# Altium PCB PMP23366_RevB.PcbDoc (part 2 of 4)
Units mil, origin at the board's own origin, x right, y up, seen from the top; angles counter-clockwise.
Board outline 6500 x 4250 mil, 4 copper layers (Top Layer 1, Inner Layer 2, Inner Layer 3, Bottom Layer 1), stack 75.824 mil thick; 370 components, 218 nets, 1221 pads, 351 vias.
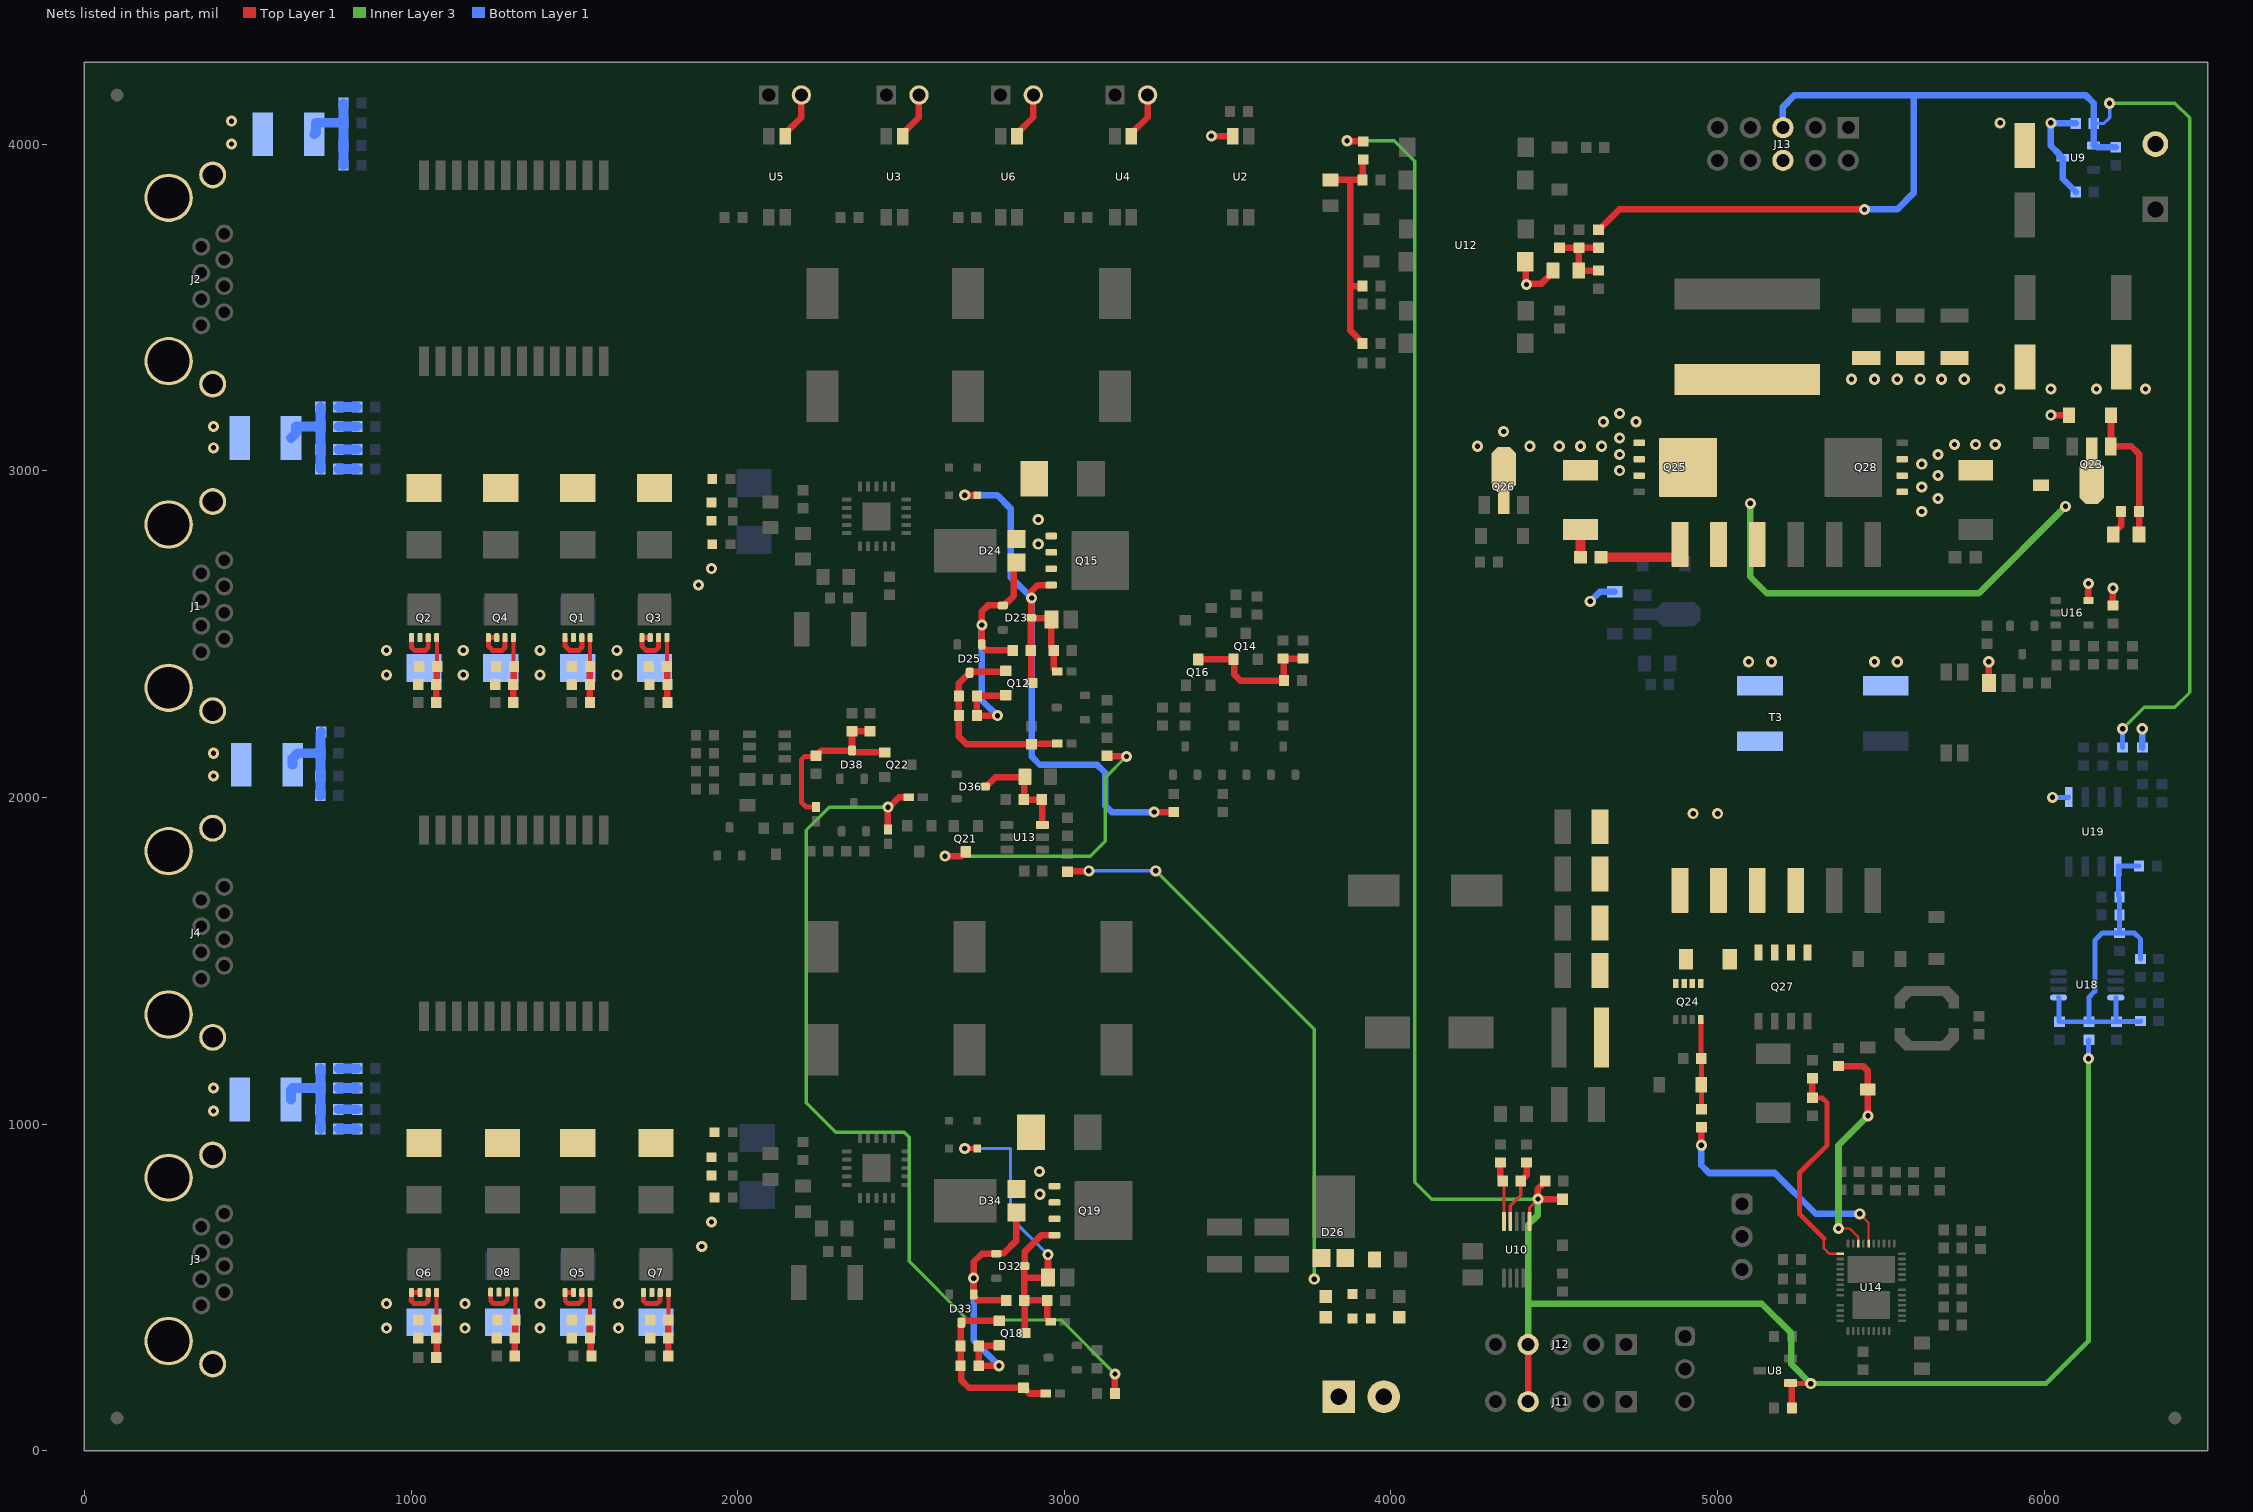
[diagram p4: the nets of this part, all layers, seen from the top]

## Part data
C1 C2 C13 C14 C39 C40: library part CMP-0007053-4, "CAP, CERM, 1000 pF, 100 V, +/- 10%, X7R, 0603", Cap_Case=0603, Manufacturer=TDK, PartNumber=C1608X7R2A102K080AA, Supplier Part Number 1=445-1298-1-ND, TempCo=X7R, Tolerance_%=10%, Value1=Unknown, Value2=100V, ValueDisplayed=1000pF
C3 C4 C5 C6 C15 C16 C17 C18: library part CMP-0007209-4, "CAP, CERM, 330 pF, 50 V, +/- 5%, C0G/NP0, 0603", Cap_Case=0603, Manufacturer=MuRata, PartNumber=GRM1885C1H331JA01D, Supplier Part Number 1=490-1439-1-ND, TempCo=C0G/NP0, Tolerance_%=5%, Value1=Unknown, Value2=50V, ValueDisplayed=330pF
C7 C8 C9 C10 C19 C20 C21 C22: library part CMP-0007468-5, "CAP, CERM, 0.01 uF, 100 V, +/- 10%, X7R, 0603", Cap_Case=0603, Manufacturer=MuRata, PartNumber=GRM188R72A103KA01D, Supplier Part Number 1=GRM188R72A103KA01D-ND, TempCo=X7R, Tolerance_%=10%, Value1=Unknown, Value2=100V, ValueDisplayed=0.01uF
C11 C12 C23 C24: library part CMP-0009438-2, "CAP, CERM, 1000 pF, 2000 V, +/- 10%, X7R, 1812", Cap_Case=1812, Manufacturer=MuRata, PartNumber=GR443QR73D102KW01L, TempCo=X7R, Tolerance_%=10%, Value1=Unknown, Value2=2000V, ValueDisplayed=1000pF
C25 C26 C34 C35 C36 C87 C88: library part CMP-0012603-3, "CAP, Polymer Hybrid, 47 uF, 80 V, +/- 20%, 36 milliohm, 10x10 SMD", Manufacturer=Panasonic, Supplier Part Number 1=P15469CT-ND, Tolerance_%=20%, Value1="36 ohm", Value2=80V, ValueDisplayed=47uF
C27 C38 C41 C57 C75: library part CMP-0007886-2, "CAP, CERM, 0.1 uF, 100 V, +/- 10%, X7R, 0805", Cap_Case=0805, Manufacturer=TDK, PartNumber=C2012X7R2A104K125AA, Supplier Part Number 1=445-1418-1-ND, TempCo=X7R, Tolerance_%=10%, Value1="0.020726 ohm", Value2=100V, ValueDisplayed=0.1uF
C28 C30 C42 C44 C56 C73 C96: library part CMP-0007432-5, "CAP, CERM, 1000 pF, 50 V, +/- 10%, X7R, 0603", Cap_Case=0603, Manufacturer=MuRata, PartNumber=GRM188R71H102KA01D, Supplier Part Number 1=490-1494-1-ND, TempCo=X7R, Tolerance_%=10%, Value1=Unknown, Value2=50V, ValueDisplayed=1000pF
C29 C43: library part CMP-0007887-2, "CAP, CERM, 0.047 uF, 100 V, +/- 10%, X7R, 0805", Cap_Case=0805, Manufacturer=TDK, PartNumber=C2012X7R2A473K125AA, Supplier Part Number 1=445-2276-1-ND, TempCo=X7R, Tolerance_%=10%, Value1="0.049089 ohm", Value2=100V, ValueDisplayed=0.047uF
C31 C55 C89: library part CMP-0007043-4, "CAP, CERM, 0.01 uF, 50 V, +/- 10%, X7R, 0603", Cap_Case=0603, Manufacturer=TDK, PartNumber=C1608X7R1H103K080AA, Supplier Part Number 1=445-1311-1-ND, TempCo=X7R, Tolerance_%=10%, Value1="0.0539 ohm", Value2=50V, ValueDisplayed=0.01uF
C32 C33 C58 C59 C60 C61 C95: library part CMP-0009232-2, "CAP, CERM, 2.2 uF, 100 V, +/- 10%, X7R, 1210", Cap_Case=1210, Manufacturer=MuRata, PartNumber=GRM32ER72A225KA35L, Supplier Part Number 1=490-3385-1-ND, TempCo=X7R, Tolerance_%=10%, Value1="0.007 ohm", Value2=100V, ValueDisplayed=2.2uF
C37: library part CMP-0012602-3, "CAP, Polymer Hybrid, 22 uF, 80 V, +/- 20%, 45 milliohm, 8x10 SMD", Manufacturer=Panasonic, Supplier Part Number 1=P15468CT-ND, Tolerance_%=20%, Value1="45 ohm", Value2=80V, ValueDisplayed=22uF
C45 C46 C47 C48 C49 C52 C53 C54 C71 C74 C80 C81 C82 C90 C91: library part CMP-0006837-4, "CAP, CERM, 0.1 uF, 50 V, +/- 10%, X7R, 0603", Cap_Case=0603, Manufacturer="Wurth Elektronik", TempCo=X7R, Tolerance_%=10%, Value1=Unknown, Value2=50V, ValueDisplayed=0.1uF
C50 C51 C86: library part CMP-0008412-2, "CAP, CERM, 1 uF, 25 V, +/- 10%, X7R, 0805", Cap_Case=0805, Manufacturer="Taiyo Yuden", Supplier Part Number 1=587-1281-1-ND, TempCo=X7R, Tolerance_%=10%, Value1=Unknown, Value2=25V, ValueDisplayed=1uF
C62 C77: library part CMP-0009294-2, "CAP, CERM, 4700 pF, 2000 V, +/- 10%, X7R, 1812", Cap_Case=1812, Manufacturer=AVX, PartNumber=1812GC472KA1, Supplier Part Number 1=581-1812GC472KA11A, TempCo=X7R, Tolerance_%=10%, Value1=Unknown, Value2=2000V, ValueDisplayed=4700pF
C63 C94: library part CMP-0006834-5, "CAP, CERM, 470 pF, 50 V, +/- 10%, X7R, 0603", Cap_Case=0603, Manufacturer="Wurth Elektronik", Supplier Part Number 1=710-885012206081, TempCo=X7R, Tolerance_%=10%, Value1=Unknown, Value2=50V, ValueDisplayed=470pF
C64: library part CMP-0008975-2, "CAP, CERM, 0.047 uF, 250 V, +/- 10%, X7R, 1206", Cap_Case=1206, Manufacturer=MuRata, Supplier Part Number 1=490-3538-1-ND, TempCo=X7R, Tolerance_%=10%, Value1=Unknown, Value2=250V, ValueDisplayed=0.047uF
C65 C66 C67: library part CMP-0012073-3, "CAP, Aluminum Polymer, 220 uF, 10 V, +/- 20%, 0.02 ohm, F61 SMD", Manufacturer=Panasonic, Supplier Part Number 1=P16445CT-ND, Tolerance_%=20%, Value1="0.02 ohm", Value2=10V, ValueDisplayed=220uF
C68 C69 C70: library part CMP-0009082-2, "CAP, CERM, 100 uF, 10 V, +/- 20%, X5R, 1210", Cap_Case=1210, Manufacturer="Wurth Elektronik", Supplier Part Number 1=399-11631-1-ND, TempCo=X5R, Tolerance_%=20%, Value1=Unknown, Value2=10V, ValueDisplayed=100uF
C72: library part CMP-0006835-4, "CAP, CERM, 4700 pF, 50 V, +/- 10%, X7R, 0603", Cap_Case=0603, Manufacturer="Wurth Elektronik", Supplier Part Number 1=710-885012206087, TempCo=X7R, Tolerance_%=10%, Value1=Unknown, Value2=50V, ValueDisplayed=4700pF
C76 C84: library part CMP-0007049-4, "CAP, CERM, 0.047 uF, 50 V, +/- 10%, X7R, 0603", Cap_Case=0603, Manufacturer=TDK, PartNumber=C1608X7R1H473K080AA, Supplier Part Number 1=445-1313-1-ND, TempCo=X7R, Tolerance_%=10%, Value1="0.049007 ohm", Value2=50V, ValueDisplayed=0.047uF
C78: library part CMP-0007220-4, "CAP, CERM, 47 pF, 50 V, +/- 5%, C0G/NP0, 0603", Cap_Case=0603, Manufacturer=MuRata, Supplier Part Number 1=490-1419-1-ND, TempCo=C0G/NP0, Tolerance_%=5%, Value1=Unknown, Value2=50V, ValueDisplayed=47pF
C79: library part CMP-0006897-4, "CAP, CERM, 2200 pF, 50 V, +/- 10%, X7R, 0603", Cap_Case=0603, Manufacturer=Kemet, Supplier Part Number 1=1362428, TempCo=X7R, Tolerance_%=10%, Value1=Unknown, Value2=50V, ValueDisplayed=2200pF
C83 C92 C93: library part CMP-0006822-4, "CAP, CERM, 100 pF, 50 V, +/- 5%, C0G/NP0, 0603", Cap_Case=0603, Manufacturer="Wurth Elektronik", TempCo=C0G/NP0, Tolerance_%=5%, Value1=Unknown, Value2=50V, ValueDisplayed=100pF
C85: library part CMP-0007451-4, "CAP, CERM, 0.033 uF, 50 V, +/- 10%, X7R, 0603", Cap_Case=0603, Manufacturer=MuRata, Supplier Part Number 1=490-3286-1-ND, TempCo=X7R, Tolerance_%=10%, Value1=Unknown, Value2=50V, ValueDisplayed=0.033uF
D1 D2 D3 D4 D5 D6 D7 D8 D9 D10 D11 D12 D13 D14 D15 D16: library part CMP-0028397-2, "Diode, Schottky, 100 V, 2 A, SMB", Manufacturer="Diodes Inc.", Value1=2A, Value2=0.79V
D17 D18 D27 D28 D37 D47 D48: library part CMP-0076979-3, "Diode, Switching, 100 V, 0.25 A, SOD-523", Manufacturer=Nexperia, Value1=0.25A, Value2=1.25V
D19 D21 D29 D30: library part CMP-0005583-3, "Diode, TVS, Uni, 58 V, 93.6 Vc, SMB", Manufacturer="Diodes Inc.", Value1=600W
D20 D36 D55: library part CMP-0005999-3, "Diode, Zener, 5.1 V, 225 mW, SOT-23", Manufacturer="ON Semiconductor", Power_W=225mW, Value1=0.225W
D22 D31 D53 D54: library part CMP-0076946-2, "Diode, Schottky, 100 V, 0.25 A, SOD-323F", Manufacturer=Nexperia, Value1=0.25A, Value2=0.85V
D23 D25 D32 D33 D38: library part CMP-0005949-3, "Diode, Zener, 10 V, 225 mW, SOT-23", Manufacturer="ON Semiconductor", Power_W=225mW, Value1=0.225W
D24 D26 D34: library part CMP-0028754-2, "Diode, Schottky, 100 V, 3 A, PowerDI5", Manufacturer="Diodes Inc.", Value1=3A, Value2=0.76V
D35: library part CMP-0002939-3, "LED, Red, SMD", Color=Red, Manufacturer=Avago, Value1=W, Value2=1.6V
D39 D41 D42 D43 D44 D45 D51: library part CMP-0029032-2, "Diode, Switching, 100 V, 0.2 A, SOD-123", Manufacturer="ON Semiconductor", PartNumber=MMSD4148T1G, Value1=0.2A, Value2=1V
D40 D52: library part CMP-0005749-3, "Diode, Zener, 10 V, 500 mW, SOD-123", Manufacturer="Diodes Inc.", PartNumber=MMSZ5240B-7-F, Power_W=500mW, Value1=0.5W
D46: library part CMP-0028456-2, "Diode, Schottky, 30 V, 0.2 A, SOT-23", Manufacturer="Diodes Inc.", Value1=0.2A, Value2=0.65V
D49 D50: library part CMP-0028524-2, "Diode, Schottky, 20 V, 0.5 A, SOD-123", Manufacturer="ON Semiconductor", Value1=0.5A, Value2=0.385V
FID1 FID2 FID3: library part CMP-0077181-1, "Fiducial mark.  There is nothing to buy or mount.", Manufacturer=N/A
J1 J2 J3 J4: library part CMP-0054918-1, "RJ45, No LED, tab up, R/A, TH", Color=Black, Manufacturer="TE Connectivity", Supplier Part Number 1=A97716-ND
J5 J6 J7 J8: library part CMP-0002337-1, "Header, 100mil, 2x1, Tin, TH", Color=Black, Current_A=3A, Manufacturer="Sullins Connector Solutions", Supplier Part Number 1=S1012E-02-ND, Voltage_V=1.8kV
J9: library part CMP-0074913-1, "Terminal Block, 3.5mm Pitch, 2x1, TH", Color=Grey, Current_A=6A, Manufacturer="On-Shore Technology", Supplier Part Number 1=ED1514-ND, Voltage_V=150V
J10: library part CMP-0079327-1, "Header, 2.54mm, 3x1, Gold, TH", Color=Black, Manufacturer=Samtec, Supplier Part Number 1=SAM1038-03-ND
J11 J12: library part CMP-0075485-1, "Header, 100mil, 5x1, Gold, TH", Manufacturer=Samtec, Supplier Part Number 1=SAM8737-ND
J13: library part CMP-0055448-2, "Header (shrouded), 100mil, 5x2, High-Temperature, Gold, TH", Manufacturer=3M, Supplier Part Number 1=MHC10K-ND
J14: library part CMP-0074910-1, "Terminal Block, 5.08 mm, 2x1, Brass, TH", Color=Blue, Current_A=15A, Manufacturer="On-Shore Technology", PartNumber=ED120/2DS, Supplier Part Number 1=ED1609-ND, Voltage_V=300V
J15: library part CMP-0075407-2, "Header, 100mil, 3x1, Gold, TH", Color=Black, Current_A=6.3A, Manufacturer=Samtec, Supplier Part Number 1=SAM1029-03-ND, Voltage_V=550V
L1 L2 L3 L4 L5 L6: library part CMP-0003425-2, "Ferrite Bead, 220 ohm @ 100 MHz, 2.2 A, 0603", Manufacturer=TDK, PartNumber=MPZ1608S221A, Supplier Part Number 1=445-1565-1-ND, Value1="0.05 ohm", Value2=2.2A, ValueDisplayed="220 ohm"
L7: library part CMP-0061003-2, "Inductor, Shielded, Composite, 3.3 µH, 8.1 A, 0.02 ohm, AEC-Q200 Grade 1, SMD", Manufacturer=Coilcraft, PartNumber=XAL5030-332MEB, Value1="0.02 ohm", Value2=8.1A, ValueDisplayed=3.3uH
L8: library part CMP-0060948-1, "Inductor, Shielded, Composite, 3.3 uH, 25 A, 0.0037 ohm, SMD", Manufacturer=Coilcraft, Supplier Part Number 1=994-XAL1010-332MEB, Value1="0.0037 ohm", Value2=25A, ValueDisplayed=3.3uH
L9: library part CMP-0062000-2, "Inductor, Shielded Drum Core, Ferrite, 2.2 mH, 0.08 A, 11 ohm, SMD", Manufacturer=Coilcraft, PartNumber=LPS5030-225MLB, Value1="11 ohm", Value2=0.08A, ValueDisplayed=2.2mH
Logo1: library part CMP-0074769-3, Manufacturer="Texas Instruments"
Logo2: library part CMP-0074847-1, "FCC_disclaimer"
Q1 Q2 Q3 Q4 Q5 Q6 Q7 Q8: library part CMP-0000969-3, "MOSFET, N-CH, 100 V, 5 A, DNH0008A (VSONP-8)", Alternate Manufacturer=None, Manufacturer="Texas Instruments", Value2="7.2 nC"
Q9 Q10 Q11 Q17 Q30: library part CMP-0000366-2, "Transistor, PNP, 100 V, 0.2 A, SOT-23", Manufacturer="Fairchild Semiconductor", Supplier Part Number 1=BSS63CT-ND, Value1="0.2 A"
Q12 Q13 Q14 Q16 Q18 Q20 Q21 Q22 Q31: library part CMP-0087176-1, "MOSFET N-CH 100V 170MA SOT23-3", Manufacturer="Diodes Incorporated"
Q15 Q19: library part CMP-0000962-2, "MOSFET, N-CH, 100 V, 10 A, DQJ0008A (VSONP-8)", Alternate Manufacturer=None, Manufacturer="Texas Instruments", Value2="17 nC"
Q23 Q29: library part CMP-0000483-2, "Transistor, NPN, 60 V, 1 A, AEC-Q101, SOT-89", Manufacturer="Diodes Inc.", Supplier Part Number 1=FCX491CT-ND, Value1="1 A", Value2=300
Q24: library part CMP-0000056-3, "MOSFET, P-CH, -150 V, -3 A, QFN-8", Alternate Manufacturer=None, Manufacturer="Fairchild Semiconductor", PartNumber=FDMC2523P, Value2="6.2 nC"
Q25 Q28: library part CMP-0000592-1, "MOSFET, N-CH, 30 V, 25 A, DQJ0008A (VSONP-8)", Alternate Manufacturer=None, Manufacturer="Texas Instruments", Supplier Part Number 1=CSD17578Q5A-ND, Value1=0.009, Value2="17.2 nC"
Q26: library part CMP-0000356-2, "Transistor, PNP, 60 V, 0.6 A, AEC-Q101, SOT-89", Manufacturer="Diodes Inc.", Supplier Part Number 1=DXT2907ADICT-ND, Value1="0.6 A", Value2=300
Q27: library part CMP-0001057-1, "MOSFET, N-CH, 150 V, 6.7 A, PQFN08A", Alternate Manufacturer=None, Manufacturer="Fairchild Semiconductor", Supplier Part Number 1=FDMS86250CT-ND, Value1=0.02, Value2="36 nC"
R1 R2 R11 R12 R13 R14 R15 R16 R17 R18 R27 R28 R29 R30 R31 R32: library part CMP-0022590-4, "RES, 75.0, 1%, 0.1 W, AEC-Q200 Grade 0, 0603", Manufacturer=Vishay-Dale, PartNumber=CRCW060375R0FKEA, Power_W=100mW, Supplier Part Number 1=541-75.0HCT-ND, TempCo="100 ppm/C", Tolerance_%=1%, Value2=0.1W, Value_Code=75R0, ValueDisplayed=75.0
R3 R4 R5 R6 R19 R20 R21 R22: library part CMP-0022138-4, "RES, 1.00 M, 1%, 0.1 W, AEC-Q200 Grade 0, 0603", Manufacturer=Vishay-Dale, PartNumber=CRCW06031M00FKEA, Power_W=100mW, Supplier Part Number 1=541-1.00MHCT-ND, TempCo="100 ppm/C", Tolerance_%=1%, Value2=0.1W, Value_Code=1M00, ValueDisplayed=1.00M
R7 R8 R9 R10 R23 R24 R25 R26: library part CMP-0022224-4, "RES, 232 k, 1%, 0.1 W, AEC-Q200 Grade 0, 0603", Manufacturer=Vishay-Dale, PartNumber=CRCW0603232KFKEA, Power_W=100mW, Supplier Part Number 1=541-232KHCT-ND, TempCo="100 ppm/C", Tolerance_%=1%, Value2=0.1W, Value_Code=232k
R33 R86 R134: library part CMP-0022204-4, "RES, 20.0 k, 1%, 0.1 W, AEC-Q200 Grade 0, 0603", Manufacturer=Vishay-Dale, PartNumber=CRCW060320K0FKEA, Power_W=100mW, Supplier Part Number 1=541-20.0KHCT-ND, TempCo="100 ppm/C", Tolerance_%=1%, Value2=0.1W, Value_Code=20k0, ValueDisplayed=20.0k
R34 R60: library part CMP-0022254-4, "RES, 27.4 k, 1%, 0.1 W, AEC-Q200 Grade 0, 0603", Manufacturer=Vishay-Dale, PartNumber=CRCW060327K4FKEA, Power_W=100mW, Supplier Part Number 1=541-27.4KHCT-ND, TempCo="100 ppm/C", Tolerance_%=1%, Value2=0.1W, Value_Code=27k4, ValueDisplayed=27.4k
R35 R51 R52 R54 R78 R91 R97 R104 R107 R131: library part CMP-0021998-4, "RES, 10.0 k, 1%, 0.1 W, AEC-Q200 Grade 0, 0603", Manufacturer=Vishay-Dale, PartNumber=CRCW060310K0FKEA, Power_W=100mW, Supplier Part Number 1=541-10.0KHCT-ND, TempCo="100 ppm/C", Tolerance_%=1%, Value2=0.1W, Value_Code=10k0, ValueDisplayed=10.0k
R36 R38 R39 R41 R61 R63 R85 R87 R135: library part CMP-0021990-4, "RES, 100 k, 1%, 0.1 W, AEC-Q200 Grade 0, 0603", Manufacturer=Vishay-Dale, PartNumber=CRCW0603100KFKEA, Power_W=100mW, Supplier Part Number 1=541-100KHCT-ND, TempCo="100 ppm/C", Tolerance_%=1%, Value2=0.1W, Value_Code=100k
R37 R62 R133: library part CMP-0022040-4, "RES, 137 k, 1%, 0.1 W, AEC-Q200 Grade 0, 0603", Manufacturer=Vishay-Dale, PartNumber=CRCW0603137KFKEA, Power_W=100mW, Supplier Part Number 1=541-137KHCT-ND, TempCo="100 ppm/C", Tolerance_%=1%, Value2=0.1W, Value_Code=137k
R40 R64 R102: library part CMP-0022532-4, "RES, 60.4 k, 1%, 0.1 W, AEC-Q200 Grade 0, 0603", Manufacturer=Vishay-Dale, Power_W=100mW, Supplier Part Number 1=541-60.4KHCT-ND, TempCo="100 ppm/C", Tolerance_%=1%, Value2=0.1W, Value_Code=60k4, ValueDisplayed=60.4k
R42 R43: library part CMP-0022133-4, "RES, 1.78 k, 1%, 0.1 W, AEC-Q200 Grade 0, 0603", Manufacturer=Vishay-Dale, PartNumber=CRCW06031K78FKEA, Power_W=100mW, Supplier Part Number 1=541-1.78KHCT-ND, TempCo="100 ppm/C", Tolerance_%=1%, Value2=0.1W, Value_Code=1k78, ValueDisplayed=1.78k
R44 R65: library part CMP-0016077-3, "RES, 1.3 k, 5%, 0.75 W, AEC-Q200 Grade 0, 2010", Manufacturer=Vishay-Dale, Power_W=750mW, Supplier Part Number 1=541-1.3KWCT-ND, TempCo="200 ppm/C", Tolerance_%=5%, Value2=0.75W, Value_Code=1k30, ValueDisplayed=1.3k
R45 R50: library part CMP-0022426-4, "RES, 44.2 k, 1%, 0.1 W, AEC-Q200 Grade 0, 0603", Manufacturer=Vishay-Dale, PartNumber=CRCW060344K2FKEA, Power_W=100mW, Supplier Part Number 1=541-44.2KHCT-ND, TempCo="100 ppm/C", Tolerance_%=1%, Value2=0.1W, Value_Code=44k2, ValueDisplayed=44.2k
R46 R66: library part CMP-0022447-4, "RES, 49.9 k, 1%, 0.1 W, AEC-Q200 Grade 0, 0603", Manufacturer=Vishay-Dale, PartNumber=CRCW060349K9FKEA, Power_W=100mW, Supplier Part Number 1=541-49.9KHCT-ND, TempCo="100 ppm/C", Tolerance_%=1%, Value2=0.1W, Value_Code=49k9, ValueDisplayed=49.9k
R47 R67: library part CMP-0021376-3, "RES, 63.4, 1%, 0.125 W, AEC-Q200 Grade 0, 0805", Manufacturer=Vishay-Dale, PartNumber=CRCW080563R4FKEA, Power_W=125mW, Supplier Part Number 1=541-63.4CCT-ND, TempCo="100 ppm/C", Tolerance_%=1%, Value2=0.125W, Value_Code=63R4, ValueDisplayed=63.4
R48 R68: library part CMP-0021073-3, "RES, 249, 1%, 0.125 W, AEC-Q200 Grade 0, 0805", Manufacturer=Vishay-Dale, Power_W=125mW, Supplier Part Number 1=541-249CCT-ND, TempCo="100 ppm/C", Tolerance_%=1%, Value2=0.125W, Value_Code=249R, ValueDisplayed=249
R49 R69 R88: library part CMP-0022324-4, "RES, 30.1 k, 1%, 0.1 W, AEC-Q200 Grade 0, 0603", Manufacturer=Vishay-Dale, PartNumber=CRCW060330K1FKEA, Power_W=100mW, Supplier Part Number 1=541-30.1KHCT-ND, TempCo="100 ppm/C", Tolerance_%=1%, Value2=0.1W, Value_Code=30k1, ValueDisplayed=30.1k
R53 R76 R77 R98 R114: library part CMP-0022109-5, "RES, 1.00 k, 1%, 0.1 W, AEC-Q200 Grade 0, 0603", Manufacturer=Vishay-Dale, PartNumber=CRCW06031K00FKEA, Power_W=100mW, Supplier Part Number 1=541-1.00KHCT-ND, TempCo="100 ppm/C", Tolerance_%=1%, Value2=0.1W, Value_Code=1k00, ValueDisplayed=1.00k
R55 R56 R57 R58: library part CMP-0023050-5, "RES, 35.7 k, 1%, 0.1 W, 0603", Manufacturer=Yageo, Power_W=100mW, Supplier Part Number 1=311-35.7KHRCT-ND, TempCo="100 ppm/C", Tolerance_%=1%, Value2=0.1W, Value_Code=35k7, ValueDisplayed=35.7k
R59: library part CMP-0021998-4, "RES, 10.0 k, 1%, 0.1 W, AEC-Q200 Grade 0, 0603", Manufacturer=Vishay-Dale, Power_W=100mW, Supplier Part Number 1=541-10.0KHCT-ND, TempCo="100 ppm/C", Tolerance_%=1%, Value2=0.1W, Value_Code=10k0, ValueDisplayed=10.0k
R70 R74 R75 R79 R81 R115 R116 R117 R118 R125 R126 R127 R129: library part CMP-0025697-4, "RES, 0, 5%, 0.1 W, AEC-Q200 Grade 0, 0603", Manufacturer=Vishay-Dale, Power_W=100mW, Supplier Part Number 1=541-0.0GCT-ND, TempCo="200 ppm/C", Tolerance_%=5%, Value2=0.1W, Value_Code=0000, ValueDisplayed=0
R71: library part CMP-0080609-1, "RES, 0.025, 1%, 0.125 W, AEC-Q200 Grade 1, 0805", Manufacturer="Yageo America", Power_W=125mW, Supplier Part Number 1=311-.10SCT-ND, TempCo="600 ppm/C", Tolerance_%=1%, Value2=0.125W, Value_Code=R100, ValueDisplayed=0.1
R72 R73: library part CMP-0025754-4, "RES, 20, 5%, 0.1 W, AEC-Q200 Grade 0, 0603", Manufacturer=Vishay-Dale, Power_W=100mW, Supplier Part Number 1=541-20GCT-ND, TempCo="200 ppm/C", Tolerance_%=5%, Value2=0.1W, Value_Code=20R0, ValueDisplayed=20
R80: library part CMP-0022066-4, "RES, 15.0 k, 1%, 0.1 W, AEC-Q200 Grade 0, 0603", Manufacturer=Vishay-Dale, Power_W=100mW, Supplier Part Number 1=541-15.0KHCT-ND, TempCo="100 ppm/C", Tolerance_%=1%, Value2=0.1W, Value_Code=15k0, ValueDisplayed=15.0k
R82 R109: library part CMP-0022458-4, "RES, 4.99 k, 1%, 0.1 W, AEC-Q200 Grade 0, 0603", Manufacturer=Vishay-Dale, Power_W=100mW, Supplier Part Number 1=541-4.99KHCT-ND, TempCo="100 ppm/C", Tolerance_%=1%, Value2=0.1W, Value_Code=4k99, ValueDisplayed=4.99k
R83 R119 R120 R121 R122 R123 R124 R128: library part CMP-0025817-4, "RES, 4.7 k, 5%, 0.1 W, AEC-Q200 Grade 0, 0603", Manufacturer=Vishay-Dale, Power_W=100mW, Supplier Part Number 1=541-4.7KGCT-ND, TempCo="200 ppm/C", Tolerance_%=5%, Value2=0.1W, Value_Code=4k70, ValueDisplayed=4.7k
R84 R130: library part CMP-0020536-3, "RES, 39 k, 5%, 0.125 W, AEC-Q200 Grade 0, 0805", Manufacturer=Vishay-Dale, Power_W=125mW, Supplier Part Number 1=541-39KACT-ND, TempCo="200 ppm/C", Tolerance_%=5%, Value2=0.125W, Value_Code=39k0, ValueDisplayed=39k
R89 R136: library part CMP-0022110-4, "RES, 1.02 k, 1%, 0.1 W, AEC-Q200 Grade 0, 0603", Manufacturer=Vishay-Dale, PartNumber=CRCW06031K02FKEA, Power_W=100mW, Supplier Part Number 1=541-1.02KHCT-ND, TempCo="100 ppm/C", Tolerance_%=1%, Value2=0.1W, Value_Code=1k02, ValueDisplayed=1.02k
R90 R132: library part CMP-0021282-3, "RES, 499, 1%, 0.125 W, AEC-Q200 Grade 0, 0805", Manufacturer=Vishay-Dale, Power_W=125mW, Supplier Part Number 1=541-499CCT-ND, TempCo="100 ppm/C", Tolerance_%=1%, Value2=0.125W, Value_Code=499R, ValueDisplayed=499
R92: library part CMP-0025703-4, "RES, 10, 5%, 0.1 W, AEC-Q200 Grade 0, 0603", Manufacturer=Vishay-Dale, PartNumber=CRCW060310R0JNEA, Power_W=100mW, Supplier Part Number 1=541-10GCT-ND, TempCo="200 ppm/C", Tolerance_%=5%, Value2=0.1W, Value_Code=10R0, ValueDisplayed=10
R93 R96: library part CMP-0016161-3, "RES, 5.1, 5%, 0.75 W, AEC-Q200 Grade 0, 2010", Manufacturer=Vishay-Dale, Power_W=750mW, Supplier Part Number 1=541-5.1WCT-ND, TempCo="200 ppm/C", Tolerance_%=5%, Value2=0.75W, Value_Code=5R10, ValueDisplayed=5.1
R94: library part CMP-0025703-4, "RES, 10, 5%, 0.1 W, AEC-Q200 Grade 0, 0603", Manufacturer=Vishay-Dale, Power_W=100mW, Supplier Part Number 1=541-10GCT-ND, TempCo="200 ppm/C", Tolerance_%=5%, Value2=0.1W, Value_Code=10R0, ValueDisplayed=10
R95: library part CMP-0022655-4, "RES, 93.1 k, 1%, 0.1 W, AEC-Q200 Grade 0, 0603", Manufacturer=Vishay-Dale, Power_W=100mW, Supplier Part Number 1=541-93.1KHCT-ND, TempCo="100 ppm/C", Tolerance_%=1%, Value2=0.1W, Value_Code=93k1, ValueDisplayed=93.1k
R99: library part CMP-0065760-2, "RES, 0.068, 1%, .5 W, AEC-Q200 Grade 0, 2010", Manufacturer=Rohm, Power_W=500mW, Supplier Part Number 1=RHM.068VCT-ND, TempCo="800 ppm/C", Tolerance_%=1%, Value2=.5W, Value_Code=R068, ValueDisplayed=0.068
R100: library part CMP-0022226-4, "RES, 237 k, 1%, 0.1 W, AEC-Q200 Grade 0, 0603", Manufacturer=Vishay-Dale, Power_W=100mW, Supplier Part Number 1=541-237KHCT-ND, TempCo="100 ppm/C", Tolerance_%=1%, Value2=0.1W, Value_Code=237k
R101: library part CMP-0025697-4, "RES, 0, 5%, 0.1 W, AEC-Q200 Grade 0, 0603", Manufacturer=Vishay-Dale, PartNumber=CRCW06030000Z0EA, Power_W=100mW, Supplier Part Number 1=541-0.0GCT-ND, TempCo="200 ppm/C", Tolerance_%=5%, Value2=0.1W, Value_Code=0000, ValueDisplayed=0
R103 R105: library part CMP-0022268-4, "RES, 2.00 k, 1%, 0.1 W, AEC-Q200 Grade 0, 0603", Manufacturer=Vishay-Dale, PartNumber=CRCW06032K00FKEA, Power_W=100mW, Supplier Part Number 1=541-2.00KHCT-ND, TempCo="100 ppm/C", Tolerance_%=1%, Value2=0.1W, Value_Code=2k00, ValueDisplayed=2.00k
R106: library part CMP-0022547-5, "RES, 665, 1%, 0.1 W, AEC-Q200 Grade 0, 0603", Manufacturer=Vishay-Dale, PartNumber=CRCW0603665RFKEA, Power_W=100mW, Supplier Part Number 1=541-665HCT-ND, TempCo="100 ppm/C", Tolerance_%=1%, Value2=0.1W, Value_Code=665R, ValueDisplayed=665
R108 R110: library part CMP-0022447-4, "RES, 49.9 k, 1%, 0.1 W, AEC-Q200 Grade 0, 0603", Manufacturer=Vishay-Dale, Power_W=100mW, Supplier Part Number 1=541-49.9KHCT-ND, TempCo="100 ppm/C", Tolerance_%=1%, Value2=0.1W, Value_Code=49k9, ValueDisplayed=49.9k
R111: library part CMP-0022374-4, "RES, 3.24 k, 1%, 0.1 W, AEC-Q200 Grade 0, 0603", Manufacturer=Vishay-Dale, PartNumber=CRCW06033K24FKEA, Power_W=100mW, Supplier Part Number 1=541-3.24KHCT-ND, TempCo="100 ppm/C", Tolerance_%=1%, Value2=0.1W, Value_Code=3k24, ValueDisplayed=3.24k
R112: library part CMP-0022237-4, "RES, 24.9 k, 1%, 0.1 W, AEC-Q200 Grade 0, 0603", Manufacturer=Vishay-Dale, Power_W=100mW, Supplier Part Number 1=541-24.9KHCT-ND, TempCo="100 ppm/C", Tolerance_%=1%, Value2=0.1W, Value_Code=24k9, ValueDisplayed=24.9k
R113: library part CMP-0022445-4, "RES, 499 k, 1%, 0.1 W, AEC-Q200 Grade 0, 0603", Manufacturer=Vishay-Dale, Power_W=100mW, Supplier Part Number 1=541-499KHCT-ND, TempCo="100 ppm/C", Tolerance_%=1%, Value2=0.1W, Value_Code=499k
T1 T2: library part CMP-0030597-1, "Transformer, 350 uH, SMT", Manufacturer="Wurth Elektronik", ValueDisplayed=350uH
T3: library part CMP-0087855-1, "DC/DC Transformer", Manufacturer=LinkCom
U1 U7: library part CMP-0013755-3, "IEEE 802.3bt PoE High-Power PD Interface with Automatic MPS & Autoclass, RGW0020B (VQFN-20)", Alternate Manufacturer="Texas Instruments", Alternate PartNumber=TPS2372-3RGWT, Operating Temperature Range="-40 to 125 C"
U2 U3 U4 U5 U6 U15: library part CMP-0006166-3, "Optocoupler, 3.75 kV, 80-160% CTR, SMT", Manufacturer=Vishay-Semiconductor, Supplier Part Number 1=TCMT1107CT-ND, Voltage_Isolation_Vrms=3.75kV
U8 U9: library part CMP-0074892-1, "100-mA, 30-V, Fixed-Output, Linear-Voltage Regulator, DBZ0003A (SOT-23-3)", Alternate Manufacturer="Texas Instruments", Alternate PartNumber=TLV76050DBZT
U10: library part CMP-0088571-2, "High-Voltage, Zero-Drift, 16-Bit ADC, I 2C, Bidirectional Shunt Current, Bus Voltage, Power, and Temperature Monitor", Manufacturer="Texas Instruments", Operating Temperature Range=to
U11 U12 U17: library part CMP-0006165-3, "Optocoupler, 5 kV, 300-600% CTR, SMT", Manufacturer="Fairchild Semiconductor", Supplier Part Number 1=FOD817DS-ND, Voltage_Isolation_Vrms=5kV
U13 U20: library part CMP-0032355-1, "Low Quiescent Current, Programmable-Delay Supervisory Circuit, 1 Supply Monitored, -40 to 125 degC, 6-pin SOT-23 (DBV), Green (RoHS & no Sb/Br)", Manufacturer="Texas Instruments", Rating=Catalog, Threshold Voltage 1 (typ)(Typ)(V)=Adjustable
U14: library part CMP-0089621-1, "IEEE 802.3bt Type 3 Class 1-4 PoE PD with High Efficiency DC-DC Controller", Manufacturer="Texas Instruments", Operating Temperature Range="-40°C to +125°C", Switching Frequency=250kHz
U16: library part CMP-0032952-1, "Low Voltage Adjustable Precision Shunt Regulator, 39 ppm / degC, 15 mA, -40 to 85 degC, 5-pin SOT-23 (DBV), Green (RoHS & no Sb/Br)", Manufacturer="Texas Instruments", Rating=Catalog, Temp Coeff(Max)(ppm/ degree C)=129, Temp Coeff(Typ)(ppm/ degree C)=39
U18: library part CMP-0065788-2, "Level-Translating I2C Bus Repeater, DGK0008A (VSSOP-8)", Alternate Manufacturer="Texas Instruments"
U19: library part CMP-0091761-1, Digikey Part Number=296-ISO1640BDRCT-ND, Manufacturer="Texas Instruments", Max Supply Voltage=5.5V, Min Supply Voltage=2.25V, Mouser Part Number=595-ISO1640BDR, Nominal Supply Current=2.7-5.3mA, Operating Temperature Range="-40°C to +125°C"

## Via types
v1: diameter 34, hole 16, Top Layer 1 to Bottom Layer 1, tented both sides, 307 vias
v2: diameter 19.68, hole 7.87, Top Layer 1 to Bottom Layer 1, 23 vias
v3: diameter 34, hole 16, Top Layer 1 to Bottom Layer 1, 21 vias

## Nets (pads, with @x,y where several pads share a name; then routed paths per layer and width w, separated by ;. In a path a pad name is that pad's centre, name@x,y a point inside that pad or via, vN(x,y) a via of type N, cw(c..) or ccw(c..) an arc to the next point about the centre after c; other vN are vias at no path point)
5V_PRI: C46.1 C54.1 D35.2 J11.4 J12.4 R74.1 R117.2 U8.1 U10.6 | length 7644.7
  Top Layer 1 w10: U10.6@4424.37,701.61 4424.37,744.37 v1(4450,770)
  Top Layer 1 w15: U8.1@5227.56,205.21 5228.36,206.01 5283.99,206.01 v1(5285,205)
  Top Layer 1 w20: v1(3865,4010) 3866.22,4008.78 3913.78,4008.78 R74.1@3915,4007.56 ; J11.4@4420,150 J12.4@4420,325 ; C54.1@4472.44,825 4472.44,824.02 4450,801.57 v1(4450,770) 4450.08,770.08 4524.92,770.08 D35.2@4525,770.16 ; C46.1@5227.56,130 U8.1@5227.56,205.21
  Inner Layer 3 w10: v1(3865,4010) 4010,4010 4072.84,3947.16 4072.84,822.16 4125,770 v1(4450,770)
  Inner Layer 3 w15: v1(5285,205) 6005,205 6135,335 v1(6135,1200)
  Inner Layer 3 w20: J11.4@4418.31,148.31 J11.4@4420,150 ; J12.4@4420,325 4420,450 ; v1(4450,770) 4450,721.3 4420,691.3 4420,450 ; v1(5285,205) 5225,265 5225,360 5135,450 4420,450
  Bottom Layer 1 w15: v1(6135,1200) 6135.65,1200.65 6135.65,1257.34 R117.2@6136.3,1257.99
5V_SEC: C48.1 J13.5 R70.2 R75.1 R118.2 U9.1 | length 4982.6
  Top Layer 1 w20: R75.1@4635.61,3737.56 4636.59,3737.56 4699.04,3800 v1(5450,3800)
  Inner Layer 3 w10: v1(6200,4125) 6400,4125 6445,4080 6445,2320.94 6400,2275.94 6305.94,2275.94 v1(6240,2210)
  Bottom Layer 1 w10: C48.1@6151.3,4062.84 6182.52,4062.84 6200,4080.32 v1(6200,4125)
  Bottom Layer 1 w15: R118.2@6240,2152.56 v1(6240,2210)
  Bottom Layer 1 w20: J13.5@5200,4050 5200,4113.7 5236.3,4150 5600,4150 ; v1(5450,3800) 5550,3800 5600,3850 5600,4150 ; R70.2@6218.74,3990.56 6163.7,3990.56 6158.85,3995.4 U9.1@6150.98,3995.4 6151.14,3995.56 6151.14,4062.84 C48.1@6151.3,4063 6151.3,4125 6126.3,4150 5600,4150
AUX: C38.1 C39.1 D26.1 D26.2 L5.2 R87.2 | length 1722
  Top Layer 1 w20: R87.2@3010,1772.44 3011.28,1773.72 3073.72,1773.72 v1(3075,1775)
  Inner Layer 3 w10: v1(3280,1775) 3765,1290 v1(3765,525)
  Bottom Layer 1 w10: v1(3075,1775) v1(3280,1775)
AUX_OUT_1: Q21.3 R37.2 | length 926.9
  Top Layer 1 w20: v3(2635,1820) 2684.94,1820 2690.81,1825.86 2692.78,1825.86 2698.52,1831.61 Q21.3@2698.52,1833.58 ; R37.2@3130,2127.44 3131.22,2126.22 3188.78,2126.22 v3(3190,2125)
  Inner Layer 3 w10: v3(2635,1820) 3080,1820 3125,1865 3125,2060 v3(3190,2125)
AUX_OUT_2: D47.2 D48.2 R62.2 | length 2829.5
  Top Layer 1 w20: D48.2@2460,1901.65 v1(2460,1970) 2463.79,1970 2493.79,2000 D47.2@2523.35,2000 ; R62.2@3155,175 v1(3155,235)
  Inner Layer 3 w10: v1(2460,1970) 2280,1970 2210,1900 2210,1065 2300,975 2510,975 2525,960 2525,580 2705,400 2990,400 v1(3155,235)
BSVG: C11.1 C12.2 C23.1 C24.2 J1.9 J1.10 J1.11 J1.12 J2.9 J2.10 J2.11 J2.12 J3.9 J3.10 J3.11 J3.12 J4.9 J4.10 J4.11 J4.12
  other v1: 395,1040 395,1110 395,2065 395,2135 395,3070 395,3135 450,4000 450,4070
CS: C78.2 R98.1 U14.1 | length 680.2
  Top Layer 1 w7: 5325,650 5325,620 5342.64,602.36 U14.1@5375.51,602.36
  Top Layer 1 w15: C78.2@5290,1080 5290.45,1079.55 5320.45,1079.55 5335,1065 5335,935 5250,850 5250,725 5325,650
  Top Layer 1 w20: C78.2@5290,1080 R98.1@5290,1139.88
GAT2: C71.1 U14.41 | length 765
  Top Layer 1 w7: v1(5435,725) 5462.13,697.87 U14.41@5462.13,633.86
  Top Layer 1 w20: v1(4950,935) C71.1@4950,989.88
  Bottom Layer 1 w20: v1(4950,935) 4950,873.94 4973.94,850 5175,850 5300,725 v1(5435,725)
GATE: D43.1 R94.1 U14.43 | length 707.5
  Top Layer 1 w7: v1(5370,680) 5404.61,680 5430.63,653.98 U14.43@5430.63,633.86
  Top Layer 1 w20: R94.1@5370,1177.44 5445.06,1177.44 5460,1162.5 D43.1@5460,1105.53 v1(5460,1025)
  Inner Layer 3 w20: v1(5370,680) 5370,935 v1(5460,1025)
GND: C47.2 C48.2 C50.1 C62.2 C65.2 C66.2 C67.2 C68.1 C69.1 C70.1 C77.2 C86.1 C91.1 D40.2 D52.2 J5.2 J6.2 J7.2 J8.2 J13.6 J14.2 Q25.1 Q25.2 Q25.3 Q26.2 Q26.4 Q28.1 Q28.2 Q28.3 R93.2 R96.2 R111.1 U2.2 U3.3 U4.3 U5.3 U6.3 U9.3 U12.3 U16.5 U19.5 | length 1673.8
  Top Layer 1 w20: U5.3@2145,4024.02 2145,4031.89 2195,4081.89 J7.2@2195,4150 ; U3.3@2505,4024.02 2505,4031.89 2555,4081.89 J5.2@2555,4150 ; U6.3@2855,4024.02 2855,4031.89 2905,4081.89 J8.2@2905,4150 ; U4.3@3205,4024.02 3205,4031.89 3255,4081.89 J6.2@3255,4150 ; v1(3450,4025) 3450.49,4024.51 3514.51,4024.51 U2.2@3515,4024.02 ; Q26.2@4345,2903.07 Q26.4@4345,3005.43 ; U12.3@4411.22,3640 4413.11,3638.11 4413.11,3571.89 v1(4415,3570) 4417.68,3572.68 4460.93,3572.68 4495.89,3607.64 C50.1@4495.89,3612.56 ; v1(5830,2415) 5830.47,2414.53 5830.47,2350.47 C86.1@5830.94,2350 ; v1(6020,3170) D40.2@6075.53,3170 ; v1(6135,2655) 6135.1,2654.9 6135.1,2602.5 U16.5@6135.2,2602.4 ; R111.1@6210,2587.56 v1(6210,2640)
  Bottom Layer 1 w15: v1(6025,2000) 6073.7,2000 U19.5@6075,2001.3
  Bottom Layer 1 w20: v1(4610,2600) 4639.47,2629.47 D52.2@4685,2629.47 ; C47.2@6096.18,3853 6096.18,3853.98 6056.49,3893.67 U9.3@6056.49,3958 6048.62,3958 6046.81,3959.81 6046.81,3967.69 6020,3994.49 v1(6020,4064.93) 6020.96,4063.96 6095.21,4063.96 C48.2@6096.18,4063 ; C91.1@6300,2152.56 v1(6300,2210)
  other v1: 5095,2415 5165,2415 5480,2415 5550,2415 5625,2875 5675,2915 5625,2950 5675,2985 4700,3000 5625,3020 4700,3050 5675,3050 4265,3075 4425,3075 4515,3075 4580,3075 4645,3075 5725,3080 5790,3080 5850,3080 4700,3100 4345,3120 4650,3150 4750,3150 4700,3175 5865,3250 6020,3250 6160,3250 6310,3250 5410,3280 5480,3280 5550,3280 5620,3280 5685,3280 5755,3280 5865,4064.93
NetC1_1: C1.1 D1.1 D2.1 D3.1 D4.1 L1.1
NetC1_2: C1.2 C3.2 C4.2 C5.2 C6.2 D5.2 D6.2 D7.2 D8.2 L2.1 Q1.1 Q1.2 Q1.3 Q2.1 Q2.2 Q2.3 Q3.1 Q3.2 Q3.3 Q4.1 Q4.2 Q4.3 R7.1 R8.1 R9.1 R10.1 | length 518.5
  Top Layer 1 w15: Q2.1@1001.61,2488.98 1001.61,2458.79 1010.4,2450 1044.01,2450 1052.8,2458.79 Q2.3@1052.8,2488.98 ; Q4.2@1262.2,2488.98 Q4.1@1236.61,2488.98 1236.61,2463.31 1249.92,2450 1279.01,2450 1287.8,2458.79 Q4.3@1287.8,2488.98 ; Q1.1@1471.61,2488.98 1471.61,2463.39 1485,2450 1514.01,2450 1522.8,2458.79 Q1.3@1522.8,2488.98 ; Q3.2@1732.2,2488.98 Q3.1@1706.61,2488.98 1706.61,2463.31 1719.92,2450 1749.01,2450 1757.8,2458.79 Q3.3@1757.8,2488.98
  other v1: 925,2375 1160,2375 1395,2375 1630,2375 925,2450 1160,2450 1395,2450 1630,2450 1880,2650 1920,2700
NetC3_1: C3.1 Q3.4 R3.2 R7.2 | length 200
  Top Layer 1 w12: C3.1@1782.97,2400.41 1782.97,2488.56 Q3.4@1783.39,2488.98
  Top Layer 1 w20: C3.1@1782.97,2400.41 1783.78,2399.61 1783.78,2346.22 R7.2@1785,2345 R3.2@1785,2290
NetC4_1: C4.1 Q1.4 R5.2 R8.2 | length 199.3
  Top Layer 1 w12: C4.1@1547.97,2400.41 1547.97,2488.56 Q1.4@1548.39,2488.98
  Top Layer 1 w20: R5.2@1547.56,2290 R8.2@1547.56,2345 C4.1@1547.56,2400 C4.1@1547.97,2400.41
NetC5_1: C5.1 Q4.4 R4.2 R9.2 | length 200.7
  Top Layer 1 w12: Q4.4@1313.39,2488.98 1314.19,2488.17 1314.19,2400.81 C5.1@1315,2400
  Top Layer 1 w20: R4.2@1312.56,2290 R9.2@1312.56,2345 1313.78,2346.22 1313.78,2398.78 C5.1@1315,2400
NetC6_1: C6.1 Q2.4 R6.2 R10.2 | length 200
  Top Layer 1 w12: Q2.4@1078.39,2488.98 1079.19,2488.17 C6.1@1079.19,2400.81
  Top Layer 1 w20: R6.2@1077.56,2290 R10.2@1077.56,2345 1078.78,2346.22 1078.78,2400.39 C6.1@1079.19,2400.81
NetC7_2: C7.2 R13.2 | length 57.4
  Bottom Layer 1 w30: R13.2@777.56,3005 C7.2@835,3005
NetC8_2: C8.2 R14.2 | length 57.4
  Bottom Layer 1 w30: R14.2@777.56,3065 C8.2@835,3065
NetC9_2: C9.2 R15.2 | length 57.4
  Bottom Layer 1 w30: R15.2@777.56,3135 C9.2@835,3135
NetC10_2: C10.2 R16.2 | length 57.4
  Bottom Layer 1 w30: R16.2@777.56,3195 C10.2@835,3195
NetC11_2: C11.2 R1.1 R2.1 R11.1 R12.1 | length 312
  Bottom Layer 1 w30: C11.2@703.54,4030 708.66,4035.12 708.66,4065 R2.1@793.5,4065 ; R12.1@793.5,3935 R11.1@793.5,3995 R2.1@793.5,4065 ; R1.1@793.5,4125 R2.1@793.5,4065
NetC12_1: C12.1 R13.1 R14.1 R15.1 R16.1 | length 305.7
  Bottom Layer 1 w30: C12.1@632.48,3100 648.23,3115.75 648.23,3135 R15.1@722.44,3135 ; R13.1@722.44,3005 R14.1@722.44,3065 R15.1@722.44,3135 ; R16.1@722.44,3195 R15.1@722.44,3135
NetC13_1: C13.1 D9.1 D10.1 D11.1 D12.1 L3.1
NetC13_2: C13.2 C15.2 C16.2 C17.2 C18.2 D13.2 D14.2 D15.2 D16.2 L4.1 Q5.1 Q5.2 Q5.3 Q6.1 Q6.2 Q6.3 Q7.1 Q7.2 Q7.3 Q8.1 Q8.2 Q8.3 R23.1 R24.1 R25.1 R26.1 | length 487.8
  Top Layer 1 w15: Q6.2@1027.2,483.98 Q6.1@1001.61,483.98 1001.24,483.6 1001.24,463.67 1000,462.43 1000,459.46 1009.46,450 1043.63,450 1052.42,458.79 1052.42,483.6 Q6.3@1052.8,483.98 ; Q8.1@1243.82,485 1244.19,484.63 1244.19,458.41 1252.61,450 1282.2,450 1287.2,455 1287.47,455 1294.63,462.16 1294.63,484.63 Q8.3@1295,485 ; Q5.2@1497.2,483.98 Q5.1@1471.61,483.98 1471.99,483.6 1471.99,458.41 1480.4,450 1514.01,450 1522.8,458.79 Q5.3@1522.8,483.98 ; Q7.1@1711.61,483.98 1711.99,483.6 1711.99,458.41 1720.4,450 1753.63,450 1762.42,458.79 1762.42,483.6 Q7.3@1762.8,483.98
  other v1: 925,375 1165,375 1395,375 1635,375 925,450 1165,450 1395,450 1635,450 1890,625 1920,700
NetC15_1: C15.1 Q7.4 R19.2 R23.2 | length 194.3
  Top Layer 1 w12: C15.1@1787.56,400 1787.97,400.41 1787.97,483.56 Q7.4@1788.39,483.98
  Top Layer 1 w20: R19.2@1787.56,290 R23.2@1787.56,345 C15.1@1787.56,400
NetC16_1: C16.1 Q5.4 R21.2 R24.2 | length 196.4
  Top Layer 1 w12: C16.1@1547.97,400.41 1547.97,483.56 Q5.4@1548.39,483.98
  Top Layer 1 w20: C16.1@1547.97,400.41 C16.1@1547.56,400 R24.2@1547.56,345 1550.06,342.5 1550.06,292.5 R21.2@1552.56,290
NetC17_1: C17.1 Q8.4 R20.2 R25.2 | length 196.3
  Top Layer 1 w12: C17.1@1320,400 1320.3,400.3 1320.3,484.7 Q8.4@1320.59,485
  Top Layer 1 w20: R20.2@1317.56,290 R25.2@1317.56,345 1318.78,346.22 1318.78,398.78 C17.1@1320,400
NetC18_1: C18.1 Q6.4 R22.2 R26.2 | length 201.3
  Top Layer 1 w12: C18.1@1077.56,400 1077.97,400.41 1077.97,483.56 Q6.4@1078.39,483.98
  Top Layer 1 w20: R22.2@1077.56,285 1078.78,286.22 1078.78,343.78 1080,345 1078.78,346.22 1078.78,398.78 C18.1@1077.56,400
NetC19_2: C19.2 R29.2 | length 57.4
  Bottom Layer 1 w30: R29.2@777.56,985 C19.2@835,985
NetC20_2: C20.2 R30.2 | length 57.4
  Bottom Layer 1 w30: R30.2@777.56,1045 C20.2@835,1045
NetC21_2: C21.2 R31.2 | length 57.4
  Bottom Layer 1 w30: R31.2@777.56,1110 C21.2@835,1110
NetC22_2: C22.2 R32.2 | length 57.4
  Bottom Layer 1 w30: R32.2@777.56,1170 C22.2@835,1170
NetC23_2: C23.2 R17.1 R18.1 R27.1 R28.1 | length 306.7
  Bottom Layer 1 w30: C23.2@637.48,2100 637.48,2119.25 653.23,2135 R18.1@722.44,2135 ; R28.1@722.44,2005 R27.1@722.44,2065 R18.1@722.44,2135 ; R17.1@724.88,2200 724.88,2199.02 722.44,2196.57 R18.1@722.44,2135
NetC24_1: C24.1 R29.1 R30.1 R31.1 R32.1 | length 307
  Bottom Layer 1 w30: C24.1@632.48,1075 632.48,1105 637.48,1110 R31.1@722.44,1110 ; R29.1@722.44,985 R30.1@722.44,1045 R31.1@722.44,1110 ; R32.1@722.44,1170 R31.1@722.44,1110
NetC28_1: C28.1 C29.2 D18.2 D22.2 D23.3 Q12.3 Q15.4 R36.1 R38.1 | length 2130.5
  Top Layer 1 w20: v1(2695,2925) D22.2@2733.31,2925 ; Q12.3@2899.37,2350 2898.46,2350.91 2898.46,2449.09 C28.1@2897.56,2450 2897.93,2450.37 2897.93,2549.63 D23.3@2898.31,2550 ; Q15.4@2959.96,2650 2918.7,2650 2899.37,2630.67 2899.37,2551.06 D23.3@2898.31,2550 ; D18.2@2978.35,2385 2974.41,2385 2967.44,2391.97 R36.1@2967.44,2450 2967.44,2450.98 2960.47,2457.95 C29.2@2960.47,2545 2957.28,2548.19 2900.12,2548.19 D23.3@2898.31,2550 ; v1(3275,1955) R38.1@3335,1955
  Bottom Layer 1 w20: v1(2695,2925) 2795,2925 2835.55,2884.45 2835.55,2674.45 v1(2900,2610) 2900,2125 2925,2100 3100,2100 3125,2075 3125,1975 3145,1955 v1(3275,1955)
NetC28_2: C28.2 C30.2 D21.2 D23.1 D24.1 D24.2 D25.1 Q12.2 Q15.1 Q15.2 Q15.3 R49.1 | length 933.2
  Top Layer 1 w20: v1(2795,2250) R49.1@2732.56,2250 C30.2@2732.56,2310 2733.86,2311.3 2819.33,2311.3 Q12.2@2820.63,2312.6 ; D23.1@2811.69,2587.4 2765.99,2587.4 2747.4,2568.81 v1(2747.4,2527.44) D25.1@2747.4,2468.31 2747.4,2464.37 2761.77,2450 C28.2@2842.44,2450 ; D23.1@2815.63,2587.4 2845,2616.77 2845,2710.39 D24.1@2853.39,2718.78
  Bottom Layer 1 w20: v1(2747.4,2527.44) 2747.4,2297.6 v1(2795,2250)
  other v1: 2920,2775 2920,2850
NetC30_1: C30.1 D17.2 D25.3 Q12.1 R41.1 R49.2 | length 637.1
  Top Layer 1 w20: Q12.1@2820.63,2387.4 2817.78,2384.55 2711.81,2384.55 2710,2382.74 D25.3@2710,2381.69 2710,2377.76 2708.19,2375.94 2704.25,2375.94 2677.44,2349.13 C30.1@2677.44,2310 R49.2@2677.44,2250 2677.44,2185.49 2700.49,2162.44 R41.1@2900,2162.44 2901.28,2163.72 2977.07,2163.72 D17.2@2978.35,2165
NetC31_1: C31.1 Q14.1 Q16.3 R50.2 R52.2 | length 444.7
  Top Layer 1 w20: Q16.3@3410,2421.93 3410.63,2422.56 3516.97,2422.56 Q14.1@3517.6,2423.19 3520.79,2420 3520.79,2375.47 3538.7,2357.56 R50.2@3672.44,2357.56 3671.22,2358.78 3671.22,2423.78 C31.1@3670,2425 R52.2@3730,2425
NetC40_1: C40.1 J9.1 L5.1
NetC40_2: C40.2 J9.2 L6.1
NetC42_1: C42.1 C43.2 D28.2 D31.2 D32.3 Q18.3 Q19.4 R61.1 | length 1197.4
  Top Layer 1 w15: v1(2695,925) D31.2@2733.31,925
  Top Layer 1 w20: Q18.3@2879.37,360 2878.46,360.91 C42.1@2878.46,459.09 ; v1(2950,600) C43.2@2950,530 2879.8,530 2877.93,528.13 ; D28.2@2958.35,395 2954.41,395 2952.6,396.81 2952.6,400.75 2947.44,405.91 R61.1@2947.44,460 2879.37,460 C42.1@2878.46,459.09 ; Q19.4@2969.96,660 2930,660 2878.31,608.31 D32.3@2878.31,565 2877.93,564.63 2877.93,528.13 ; 2877.93,528.13 2877.93,460.37 C42.1@2877.56,460 C42.1@2878.46,459.09
  Bottom Layer 1 w10: v1(2695,925) 2835,925 2835,715 v1(2950,600)
NetC42_2: C42.2 C44.2 D30.2 D32.1 D33.1 D34.1 D34.2 Q18.2 Q19.1 Q19.2 Q19.3 R69.1 | length 939.9
  Top Layer 1 w20: v1(2800,260) R69.1@2737.56,260 C44.2@2737.56,320 2738.86,321.3 2799.33,321.3 Q18.2@2800.63,322.6 ; C42.2@2822.44,460 2736.77,460 2722.4,474.37 D33.1@2722.4,478.31 v1(2722.4,528.13) 2722.4,577.95 2746.85,602.4 D32.1@2791.69,602.4 2793.5,604.21 2814.21,604.21 2853.39,643.39 D34.1@2853.39,728.78
  Bottom Layer 1 w20: v1(2722.4,528.13) 2722.4,337.6 v1(2800,260)
  other v1: 2925,785 2923.43,855
NetC44_1: C44.1 D27.2 D33.3 Q18.1 R63.1 R69.2 | length 574
  Top Layer 1 w20: Q18.1@2800.63,397.4 2686.81,397.4 2685,395.59 D33.3@2685,391.69 2685,387.76 2682.44,385.2 C44.1@2682.44,320 R69.2@2682.44,260 2685,257.44 2685,215 2707.56,192.44 R63.1@2875,192.44 2875.98,192.44 2893.43,175 D27.2@2943.35,175
NetC49_1: C49.1 R73.2 U10.9 | length 201.4
  Top Layer 1 w10: U10.9@4365.31,701.61 4365.31,750.2 4397.56,782.44 C49.1@4397.56,825
  Top Layer 1 w20: C49.1@4397.56,825 4397.56,825.98 4415,843.43 R73.2@4415,882.44
NetC49_2: C49.2 R72.2 U10.10 | length 185.2
  Top Layer 1 w10: C49.2@4342.44,825 4345.63,821.81 U10.10@4345.63,701.61
  Top Layer 1 w20: R72.2@4335,882.44 4335,833.43 4342.44,825.98 C49.2@4342.44,825
NetC50_2: C50.2 R75.2 R77.2 R78.2 R114.2 | length 251.3
  Top Layer 1 w20: R77.2@4515.61,3682.44 R78.2@4575.61,3682.44 ; R114.2@4635.61,3612.56 C50.2@4574.63,3612.56 4575.12,3613.05 4575.12,3681.95 R78.2@4575.61,3682.44 ; R75.2@4635.61,3682.44 R78.2@4575.61,3682.44
NetC51_2: C51.2 R74.2 R76.1 R80.1 R82.1 | length 715.8
  Top Layer 1 w20: C51.2@3815,3890 3875,3890 ; R82.1@3913.05,3390 3913.05,3390.98 3875,3429.04 3875,3563.35 ; R80.1@3913.05,3565 3876.65,3565 3875,3563.35 ; R74.2@3915,3952.44 3914.03,3951.47 3914.03,3890.97 R76.1@3913.05,3890 3875,3890 ; 3875,3563.35 3875,3890
NetC52_2: C52.2 C53.1 C90.2 R117.1 R119.1 R120.2 R121.2 R122.2 R128.1 U18.1 U18.8 U19.1 | length 1145.6
  Bottom Layer 1 w15: U18.1@6043.7,1387.17 6045,1385.91 6045,1314.41 C53.1@6046.3,1313.11 R117.1@6136.3,1313.11 ; U18.8@6218.9,1387.17 6220.1,1385.96 6220.1,1314.31 C52.2@6221.3,1313.11 ; C90.2@6290,1790 6226.3,1790 U19.1@6225,1788.7 6227.5,1786.2 6227.5,1697.5 R121.2@6230,1695 R122.2@6230,1640 R128.1@6230,1585 ; R119.1@6295,1315 6294.06,1314.06 6222.24,1314.06 C52.2@6221.3,1313.11 ; R120.2@6295,1505.12 6295,1565.67 6276.3,1584.37 6230.63,1584.37 R128.1@6230,1585 ; R117.1@6136.3,1313.11 6136.3,1387.17 6155,1405.87 6155,1561.81 6178.19,1585 R128.1@6230,1585 ; R117.1@6136.3,1313.11 C52.2@6221.3,1313.11
NetC55_2: C55.2 D36.3 R84.2 R86.1 U13.6 | length 334.9
  Top Layer 1 w20: D36.3@2756.83,2032.95 2760.77,2032.95 2789.23,2061.42 2877.62,2061.42 2877.62,1994.49 R86.1@2876.08,1992.95 C55.2@2930.96,1992.95 2931.81,1992.1 2931.81,1916.2 U13.6@2932.66,1915.35
NetC56_1: C56.1 D37.2 D38.3 Q22.1 R85.1 R88.2 | length 567.3
  Top Layer 1 w15: D37.2@2240,1970.47 2209.53,1970.47 2195,1985 2195,2115 2205,2125 2237.44,2125 R85.1@2240,2127.56
  Top Layer 1 w20: R85.1@2240,2127.56 2240.98,2127.56 2256.73,2143.31 D38.3@2350,2143.31 ; R88.2@2405,2202.44 C56.1@2350,2202.44 D38.3@2350,2143.31 ; Q22.1@2450.63,2137.4 2351.97,2137.4 2350,2139.37 D38.3@2350,2143.31
NetC59_1: C59.1 C60.1 C61.1 C62.1 C95.1 L7.2 T3.1 T3.2
  other v1: 4925,1950 5000,1950
NetC63_1: C63.1 D40.1 Q23.1 R90.2 | length 437.3
  Top Layer 1 w20: D40.1@6204.47,3170 6204.26,3169.79 6204.26,3075.01 Q23.1@6204.06,3074.8 6266.3,3074.8 6290.12,3050.98 C63.1@6290.12,2875 6290.06,2874.94 6290.06,2805.06 R90.2@6290,2805
NetC63_2: C63.2 C72.2 D39.1 L8.1 Q23.2 Q23.4 Q25.5 Q25.6 Q25.7 Q25.8 Q25.9@4909.61,3010 R90.1 T3.10 T3.11 T3.12 | length 1780
  Top Layer 1 w20: Q23.4@6145,2964.57 Q23.2@6145,3066.93 ; R90.1@6211.26,2805 6211.26,2809.92 6220.94,2819.61 6223.28,2819.61 6235,2831.32 C63.2@6235,2875
  Top Layer 1 w30: C72.2@4642.99,2735 4874.13,2735 4884.72,2745.59 T3.12@4884.72,2774.53
  Inner Layer 3 w20: v1(5100,2900) 5100,2675 5150,2625 5800,2625 6065,2890 v1(6065,2890.87)
NetC64_1: C64.1 Q24.5 Q24.6 Q24.7 Q24.8
NetC64_2: C64.2 Q27.5 Q27.6 Q27.7 Q27.8 T3.3 T3.4
NetC71_2: C71.2 D41.2 Q24.4 R91.2 | length 275.6
  Top Layer 1 w15: Q24.4@4948.39,1319.88 4949.15,1319.11 4949.15,1200.85 R91.2@4950,1200 D41.2@4950,1120 C71.2@4950,1045
NetC72_1: C72.1 R93.1 | length 85
  Top Layer 1 w30: C72.1@4580,2735 R93.1@4580,2820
